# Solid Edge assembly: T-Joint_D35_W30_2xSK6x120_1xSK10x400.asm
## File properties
Author: fknapp
Template: iso metric assembly.asm
Last saved by: fknapp
Revision: 9
Application: Solid Edge
Username: fknapp
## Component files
T-Joint_D35_W30.par
SK Schraube 10x400_ohne_Gewinde_22042020.par
SK Schraube 6x120_ohne_Gewinde.par
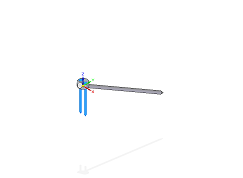
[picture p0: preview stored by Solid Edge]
